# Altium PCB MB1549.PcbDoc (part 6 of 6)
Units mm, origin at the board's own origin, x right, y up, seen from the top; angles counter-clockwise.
Board outline 70 x 133.34 mm, 6 copper layers (Top Layer, Signal Layer 1, Signal Layer 2, Signal Layer 3, Signal Layer 4, Bottom Layer), stack 1.57 mm thick; 289 components, 250 nets, 1288 pads, 875 vias.
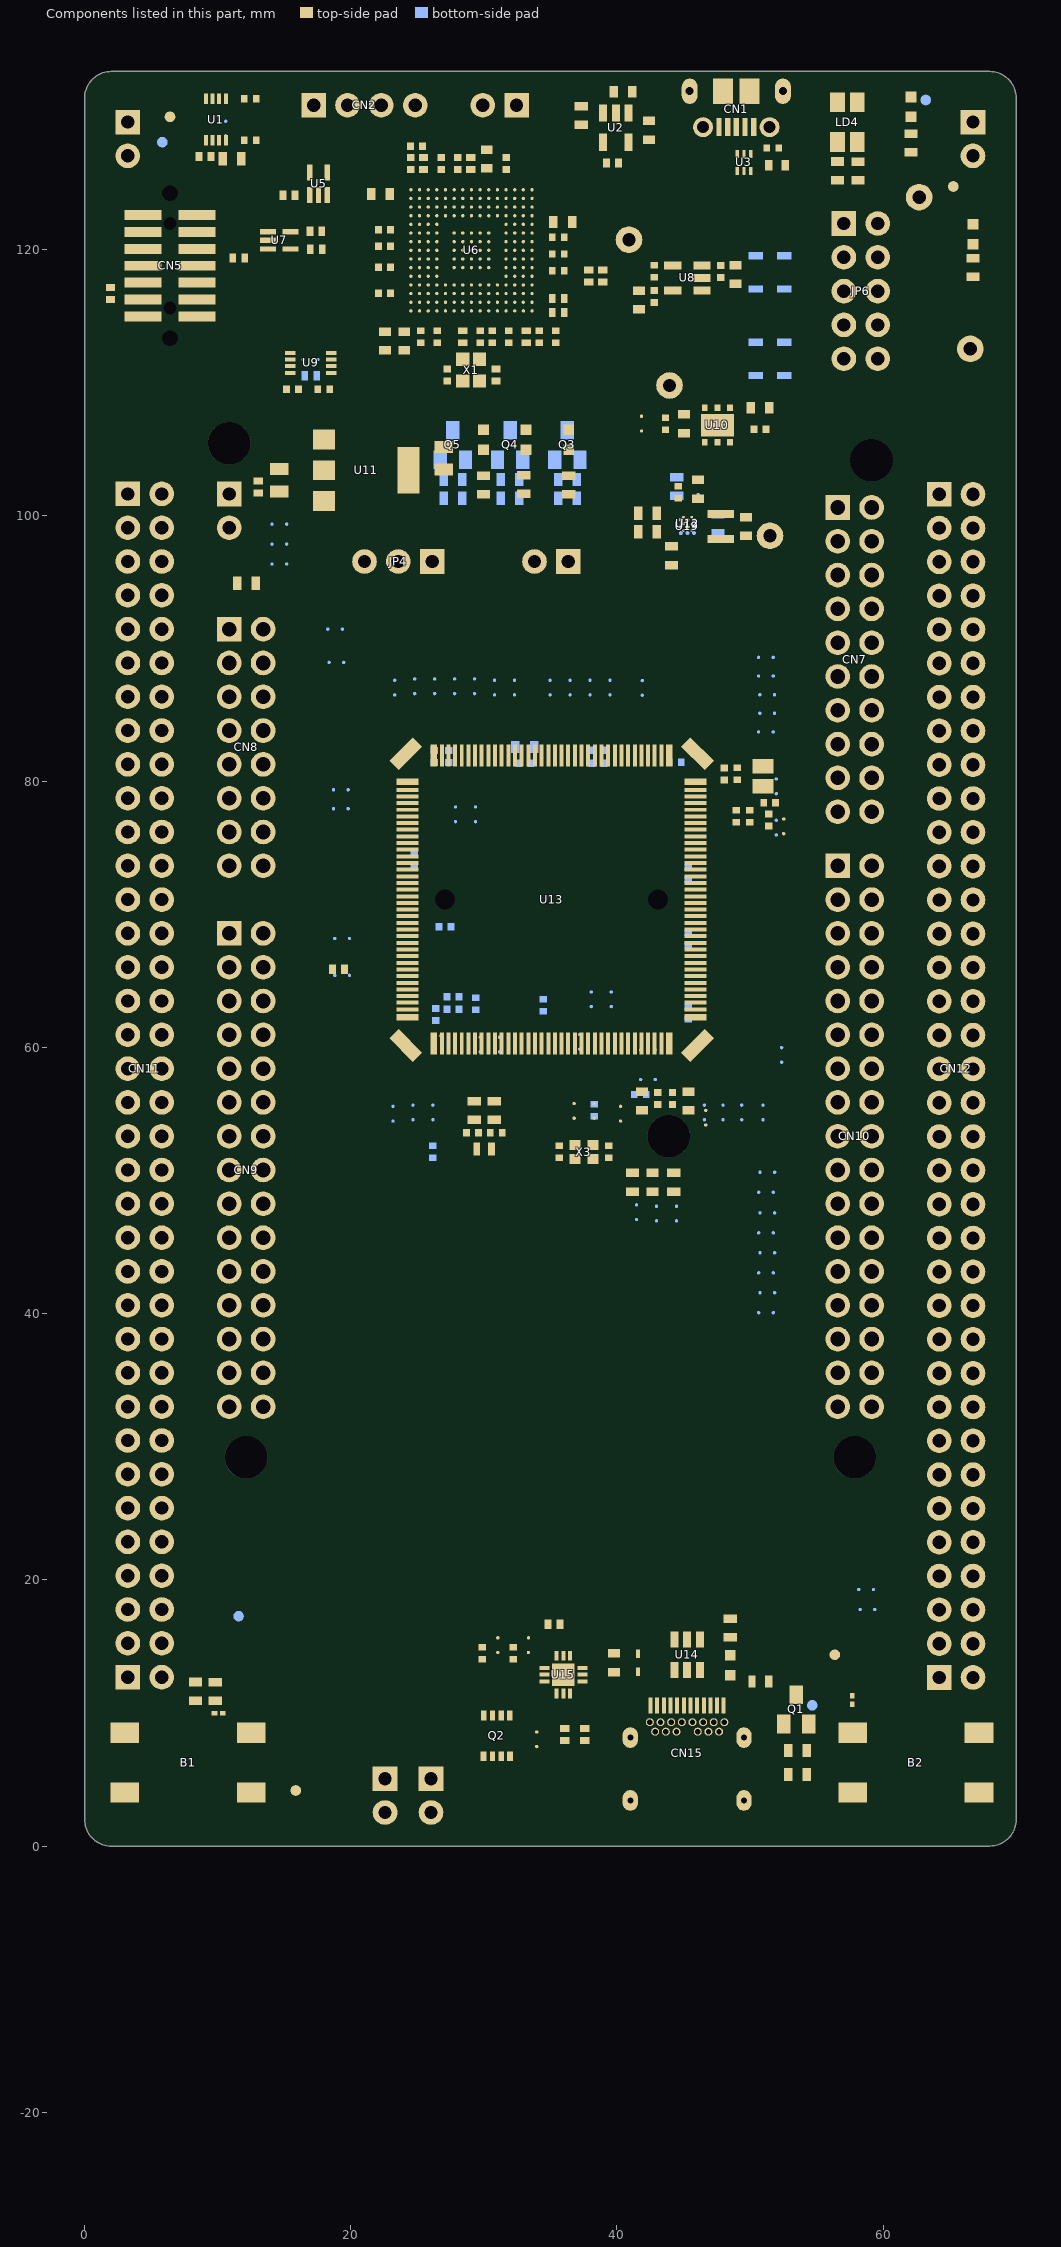
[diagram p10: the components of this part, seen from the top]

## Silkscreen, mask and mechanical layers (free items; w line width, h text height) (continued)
Drill Drawing:
  drawing of 490 lines, arcs and shapes, not listed
  text "THE COMPONENTS WITH PLATED THROUGH HOLE (PTH) MAY BE WELDED (CABLED) IN \"PIN-IN-PASTE\" MODE (IF NECESSARY)" at 62.47,163.281 h3
  text "PCB SPECIFICATIONS :" at 85.731,155.625 h3
  text "A.   MATERIAL :" at 85.731,151.625 h3
  text "FR-4" at 124.231,151.625 h3
  text "TG-170" at 140.731,151.625 h3
  text "X  TG-150" at 158.981,151.625 h3
  text "TG-140" at 174.981,151.625 h3
  text "B.   MATERIAL FAMILY :" at 85.731,148.625 h3
  text "N/A" at 124.231,148.625 h3
  text "C.   SOLDERMASK COLOR :" at 85.731,145.625 h3
  text "GREEN" at 124.231,145.625 h3
  text "X  WHITE" at 140.731,145.625 h3
  text "RED" at 158.981,145.625 h3
  text "BLACK" at 174.981,145.625 h3
  text "D.   SILKSCREEN COLOR :" at 85.731,142.625 h3
  text "WHITE" at 124.231,142.625 h3
  text "YELLOW" at 140.731,142.625 h3
  text "BLACK" at 158.981,142.625 h3
  text "X  Blue ink PANTONE 2955" at 174.981,142.625 h3
  text "E.   SURFACE FINISH :" at 85.731,139.625 h3
  text "X  ENIG" at 124.231,139.625 h3
  text "IMMERSION SILVER" at 140.731,139.625 h3
  text "IMMERSION TIN" at 174.981,139.625 h3
  text "HASL" at 124.231,136.625 h3
  text "HASL (PB-FREE)" at 140.731,136.625 h3
  text "GOLDEN FINGER" at 174.981,136.625 h3
  text "F.   IMPEDANCE CONTROL :" at 85.731,133.625 h3
  text "NO" at 124.231,133.625 h3
  text "X  YES  (SEE IMPEDANCE TABLE FOR DETAIL INFORMATION)" at 140.731,133.625 h3
  text "G.   THROUGH VIA :" at 85.731,130.625 h3
  text "PLUG THE VIAS WHICH ARE COVERED WITH SOLDERMASK ONE OR TWO SIDE." at 124.231,130.625 h3
  text "PLUG MATERIAL :" at 124.231,127.625 h3
  text "X  SOLDERMASK" at 149.731,127.625 h3
  text "NON-CONDUCTIVE EPOXY." at 174.981,127.625 h3
  text "H.   STACK-UP :" at 85.731,124.625 h3
  text "SEE LAYER STACK-UP SEQUENCE FOR OVERALL THICKNESS." at 124.231,124.625 h3
  text "Layer" at 86.896,114.381 h2
  text "Name" at 95.27,114.381 h2
  text "Material" at 111.467,114.381 h2
  text "Thickness" at 126.021,114.381 h2
  text "Constant" at 137.976,114.381 h2
  text "Board Layer Stack" at 149.04,114.381 h2
  text "Top Overlay" at 95.27,110.381 h2
  text "Top Solder" at 95.27,106.381 h2
  text "Solder Resist" at 111.467,106.381 h2
  text "0,015mm" at 126.021,106.381 h2
  text "3,5" at 137.976,106.381 h2
  text "1" at 86.896,102.381 h2
  text "Top Layer" at 95.27,102.381 h2
  text "Copper" at 111.467,102.381 h2
  text "0,042mm" at 126.021,102.381 h2
  text "Dielectric 1" at 95.27,98.381 h2
  text "FR-4" at 111.467,98.381 h2
  text "0,090mm" at 126.021,98.381 h2
  text "4,2" at 137.976,98.381 h2
  text "2" at 86.895,94.381 h2
  text "Signal Layer 1" at 95.27,94.381 h2
  text "Copper" at 111.467,94.381 h2
  text "0,035mm" at 126.021,94.381 h2
  text "Dielectric 2" at 95.27,90.381 h2
  text "0,100mm" at 126.021,90.381 h2
  text "4,2" at 137.976,90.381 h2
  text "3" at 86.896,86.381 h2
  text "Signal Layer 2" at 95.27,86.381 h2
  text "Copper" at 111.467,86.381 h2
  text "0,035mm" at 126.021,86.381 h2
  text "Dielectric 3" at 95.27,82.381 h2
  text "0,966mm" at 126.021,82.381 h2
  text "4,2" at 137.976,82.381 h2
  text "4" at 86.896,78.381 h2
  text "Signal Layer 3" at 95.27,78.381 h2
  text "Copper" at 111.467,78.381 h2
  text "0,035mm" at 126.021,78.381 h2
  text "MINIMUN PARAMETERS" at 177.004,78.289 h3
  text "Dielectric 4" at 95.27,74.381 h2
  text "0,100mm" at 126.021,74.381 h2
  text "4,2" at 137.976,74.381 h2
  text "DEFAULT" at 177.004,72.789 h3
  text "5" at 86.896,70.381 h2
  text "Signal Layer 4" at 95.27,70.381 h2
  text "Copper" at 111.467,70.381 h2
  text "0,035mm" at 126.021,70.381 h2
  text "TRACKS : 0.127 mm           / GAPS : 0.127 mm" at 177.004,67.039 h3
  text "Dielectric 5" at 95.27,66.381 h2
  text "0,090mm" at 126.021,66.381 h2
  text "4,2" at 137.976,66.381 h2
  text "6" at 86.896,62.381 h2
  text "Bottom Layer" at 95.27,62.381 h2
  text "Copper" at 111.467,62.381 h2
  text "0,042mm" at 126.021,62.381 h2
  text "IMPEDANCE" at 177.104,61.889 h3
  text "Bottom Solder" at 95.27,58.381 h2
  text "Solder Resist" at 111.467,58.381 h2
  text "0,015mm" at 126.021,58.381 h2
  text "3,5" at 137.976,58.381 h2
  text "TRACKS : 0.102 mm" at 176.97,58.081 h3
  text "Bottom Overlay" at 95.27,54.381 h2
  text "Symbol" at 86.326,47.509 h2.4
  text "Count" at 95.725,47.509 h2.4
  text "Hole Size" at 106.356,47.509 h2.4
  text "Plated" at 125.627,47.509 h2.4
  text "Drill Layer Pair" at 133.879,47.509 h2.4
  text "Via/Pad" at 156.659,47.509 h2.4
  text "Pad Shape" at 166.501,47.509 h2.4
  text "Hole Length" at 179.359,47.509 h2.4
  text "Routed Path Length" at 197.636,47.509 h2.4
  text "2" at 95.725,43.365 h2
  text "0,600mm (23,62mil)" at 106.356,43.365 h2
  text "PTH" at 125.627,43.365 h2
  text "Top Layer - Bottom Layer" at 133.879,43.365 h2
  text "Pad" at 156.659,43.365 h2
  text "Rounded" at 166.501,43.365 h2
  text "1,300mm (51,18mil)" at 179.359,43.365 h2
  text "0,700mm (27,56mil)" at 197.636,43.365 h2
  text "2" at 95.725,39.222 h2
  text "0,900mm (35,43mil)" at 106.356,39.222 h2
  text "PTH" at 125.627,39.222 h2
  text "Top Layer - Bottom Layer" at 133.879,39.222 h2
  text "Pad" at 156.659,39.222 h2
  text "Rounded" at 166.501,39.222 h2
  text "-" at 179.359,39.222 h2
  text "-" at 197.636,39.222 h2
  text "2" at 95.725,35.079 h2
  text "0,970mm (38,19mil)" at 106.356,35.079 h2
  text "NPTH" at 125.627,35.079 h2
  text "Top Layer - Bottom Layer" at 133.879,35.079 h2
  text "Pad" at 156.659,35.079 h2
  text "Rounded" at 166.501,35.079 h2
  text "-" at 179.359,35.079 h2
  text "-" at 197.636,35.079 h2
  text "2" at 95.725,30.936 h2
  text "1,190mm (46,85mil)" at 106.356,30.936 h2
  text "NPTH" at 125.627,30.936 h2
  text "Top Layer - Bottom Layer" at 133.879,30.936 h2
  text "Pad" at 156.659,30.936 h2
  text "Rounded" at 166.501,30.936 h2
  text "-" at 179.359,30.936 h2
  text "-" at 197.636,30.936 h2
  text "2" at 95.725,26.793 h2
  text "1,500mm (59,06mil)" at 106.356,26.793 h2
  text "NPTH" at 125.627,26.793 h2
  text "Top Layer - Bottom Layer" at 133.879,26.793 h2
  text "Pad" at 156.659,26.793 h2
  text "Rounded" at 166.501,26.793 h2
  text "-" at 179.359,26.793 h2
  text "-" at 197.636,26.793 h2
  text "4" at 95.725,22.65 h2
  text "0,450mm (17,72mil)" at 106.356,22.65 h2
  text "PTH" at 125.627,22.65 h2
  text "Top Layer - Bottom Layer" at 133.879,22.65 h2
  text "Pad" at 156.659,22.65 h2
  text "Rounded" at 166.501,22.65 h2
  text "0,850mm (33,47mil)" at 179.359,22.65 h2
  text "0,400mm (15,75mil)" at 197.636,22.65 h2
  text "5" at 95.725,18.507 h2
  text "3,200mm (125,98mil)" at 106.356,18.507 h2
  text "NPTH" at 125.627,18.507 h2
  text "Top Layer - Bottom Layer" at 133.879,18.507 h2
  text "Pad" at 156.659,18.507 h2
  text "Rounded" at 166.501,18.507 h2
  text "-" at 179.359,18.507 h2
  text "-" at 197.636,18.507 h2
  text "14" at 95.725,14.364 h2
  text "0,400mm (15,75mil)" at 106.356,14.364 h2
  text "PTH" at 125.627,14.364 h2
  text "Top Layer - Bottom Layer" at 133.879,14.364 h2
  text "Pad" at 156.659,14.364 h2
  text "Rounded" at 166.501,14.364 h2
  text "-" at 179.359,14.364 h2
  text "-" at 197.636,14.364 h2
  text "100" at 95.725,10.221 h2
  text "1,100mm (43,31mil)" at 106.356,10.221 h2
  text "PTH" at 125.627,10.221 h2
  text "Top Layer - Bottom Layer" at 133.879,10.221 h2
  text "Pad" at 156.659,10.221 h2
  text "Rounded" at 166.501,10.221 h2
  text "-" at 179.359,10.221 h2
  text "-" at 197.636,10.221 h2
  text "180" at 95.725,6.078 h2
  text "1,000mm (39,37mil)" at 106.356,6.078 h2
  text "PTH" at 125.627,6.078 h2
  text "Top Layer - Bottom Layer" at 133.879,6.078 h2
  text "Pad" at 156.659,6.078 h2
  text "Rounded" at 166.501,6.078 h2
  text "-" at 179.359,6.078 h2
  text "-" at 197.636,6.078 h2
  text "875" at 95.725,1.935 h2
  text "0,200mm (7,87mil)" at 106.356,1.935 h2
  text "PTH" at 125.627,1.935 h2
  text "Top Layer - Bottom Layer" at 133.879,1.935 h2
  text "Via" at 156.659,1.935 h2
  text "Rounded" at 166.501,1.935 h2
  text "-" at 179.359,1.935 h2
  text "-" at 197.636,1.935 h2
  text "1188 Total" at 95.725,-2.209 h2
  text "Slot definitions :" at 86.326,-5.109 h2
  text "Routed Path Length" at 99.979,-5.109 h2
  text "= Calculated from tool start centre position to tool end centre position." at 116.892,-5.109 h2
  text "Hole Length" at 99.979,-6.766 h2
  text "= Routed Path Length + Tool Size = Slot length as defined in the PCB layout" at 110.613,-6.766 h2

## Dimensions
66.75,101.576 to 59.126,104.139 on M2-Board Dimensions
43.89,53.341 to 72.325,0 on M2-Board Dimensions
43.89,53.341 to 59.126,104.139 on M2-Board Dimensions
0,0 to 70,0.65 on M2-Board Dimensions
3.25,12.701 to 66.75,12.676 on M2-Board Dimensions
10.87,33.021 to 59.13,33.021 on M2-Board Dimensions
12.14,29.211 to 57.86,29.211 on M2-Board Dimensions
3.25,12.701 to 2,0.001 on M2-Board Dimensions
10.87,33.021 to 3.25,12.701 on M2-Board Dimensions
12.14,29.211 to 3.25,12.701 on M2-Board Dimensions
10.87,91.441 to 3.25,101.601 on M2-Board Dimensions
3.25,101.601 to 3.246,126.999 on M2-Board Dimensions
3.246,126.999 to 3.25,12.701 on M2-Board Dimensions
3.246,129.539 to 2,133.341 on M2-Board Dimensions
43.89,53.341 to 59.126,104.139 on M2-Board Dimensions
10.866,105.409 to 59.126,104.139 on M2-Board Dimensions
68,133.341 to 68,0.001 on M2-Board Dimensions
